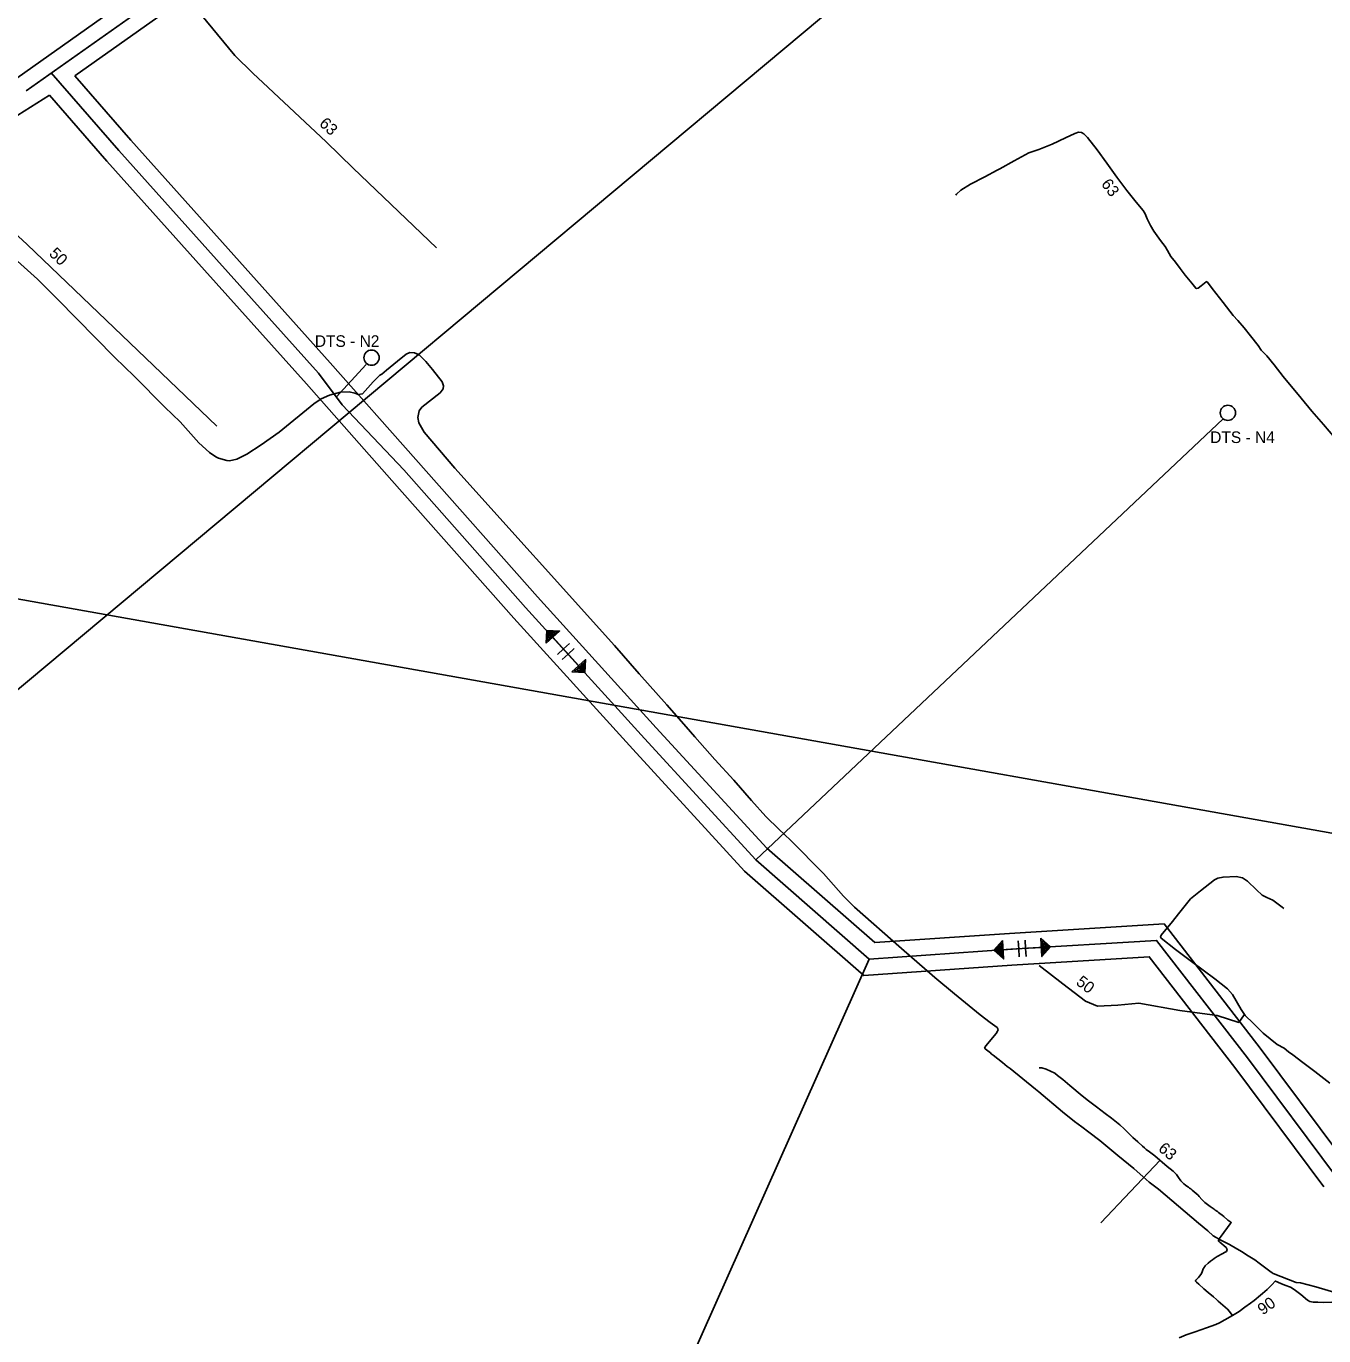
# Model space of a CAD drawing. Extents: x -444841 to -429545, y -1135312 to -1129851.
# Drawn here: x -442545 to -441650, y -1131866 to -1130962 of the extents above; entities that cross this region are included whole.
import ezdxf

# ---------------------------------------------------------------- set-up
doc = ezdxf.new("R2010")
doc.units = 0
for name, color, linetype in [('Vrstva 10', 7, 'Continuous'), ('Vrstva 15', 7, 'Continuous'), ('Vrstva 18', 7, 'Continuous'), ('Vrstva 19', 7, 'Continuous'), ('Vrstva 21', 7, 'Continuous'), ('Vrstva 27', 7, 'Continuous'), ('Vrstva 30', 7, 'Continuous'), ('Vrstva 35', 7, 'Continuous'), ('Vrstva 38', 7, 'Continuous'), ('Vrstva 58', 7, 'Continuous'), ('Vrstva 59', 7, 'Continuous')]:
    doc.layers.add(name, color=color, linetype=linetype)

msp = doc.modelspace()

# ---------------------------------------------------------------- linework, layer by layer
at = {"layer": 'Vrstva 10'}
for p, q in [((-442174.36, -1131391.7), (-442170.21, -1131387.95)), ((-442178.52, -1131395.45), (-442174.36, -1131391.7)), ((-442175.33, -1131398.99), (-442171.17, -1131395.23)), ((-442171.17, -1131395.23), (-442167.02, -1131391.48)), ((-441860.49, -1131593), (-441860.15, -1131598.59)), ((-441860.15, -1131598.59), (-441859.81, -1131604.18)), ((-441855.74, -1131592.71), (-441855.4, -1131598.3)), ((-441855.4, -1131598.3), (-441855.06, -1131603.89))]:
    msp.add_line(p, q, dxfattribs=at)
for points in [[(-442545.2, -1131006.71), (-442443.5, -1130934.6), (-442365.65, -1130877.08), (-442301.93, -1130826.75), (-442234.54, -1130772.43), (-442143.45, -1130703.1), (-442064.73, -1130644.42), (-442003.9, -1130597.89), (-441963.63, -1130563.69)], [(-441640.89, -1131756.15), (-441702.27, -1131673.76), (-441764.98, -1131592.78), (-441865.73, -1131598.93), (-441963.38, -1131605.66), (-442041.7, -1131537.14), (-442118.49, -1131453.57), (-442200.5, -1131363.12), (-442284.59, -1131268.2), (-442327.18, -1131223.28), (-442343.56, -1131201.55), (-442413.9, -1131123), (-442481.24, -1131047.9), (-442527.87, -1130994.29)], [(-442163.85, -1131403.34), (-442172.77, -1131393.47), (-442181.68, -1131383.6)], [(-441871.05, -1131599.25), (-441857.78, -1131598.44), (-441844.5, -1131597.63)]]:
    msp.add_lwpolyline(points, dxfattribs=at)
for points in [[(-442186.36, -1131387.82), (-442185.91, -1131378.92), (-442177.01, -1131379.37)], [(-442185.57, -1131386.17), (-442185.24, -1131379.65), (-442178.73, -1131379.99)], [(-442184.79, -1131384.51), (-442184.58, -1131380.39), (-442180.45, -1131380.6)], [(-442184, -1131382.86), (-442183.92, -1131381.12), (-442182.18, -1131381.21)], [(-442168.53, -1131407.56), (-442159.18, -1131399.11), (-442159.63, -1131408.01)], [(-442166.81, -1131406.95), (-442159.96, -1131400.77), (-442160.3, -1131407.28)], [(-442165.08, -1131406.33), (-442160.75, -1131402.42), (-442160.96, -1131406.54)], [(-442163.36, -1131405.72), (-442161.53, -1131404.07), (-442161.62, -1131405.81)], [(-441871.43, -1131592.97), (-441870.67, -1131605.54), (-441877.34, -1131599.64)], [(-441872.03, -1131594.7), (-441871.47, -1131603.9), (-441876.35, -1131599.58)], [(-441872.63, -1131596.43), (-441872.27, -1131602.26), (-441875.36, -1131599.52)], [(-441873.22, -1131598.16), (-441873.07, -1131600.61), (-441874.37, -1131599.46)], [(-441844.88, -1131591.35), (-441838.21, -1131597.25), (-441844.12, -1131603.92)], [(-441844.08, -1131592.99), (-441839.2, -1131597.31), (-441843.52, -1131602.19)], [(-441843.28, -1131594.63), (-441840.19, -1131597.37), (-441842.92, -1131600.46)], [(-441842.48, -1131596.28), (-441841.18, -1131597.43), (-441842.33, -1131598.73)]]:
    msp.add_lwpolyline(points, close=True, dxfattribs=at)
at = {"layer": 'Vrstva 15'}
for points in [[(-441968.62, -1130553.5), (-442010.81, -1130589.32), (-442071.36, -1130635.64), (-442150.07, -1130694.32), (-442241.33, -1130763.77), (-442308.79, -1130818.15), (-442372.32, -1130868.34), (-442449.95, -1130925.69), (-442551.7, -1130997.84)], [(-442511.53, -1130996.32), (-442437.05, -1130943.51), (-442358.97, -1130885.82), (-442295.07, -1130835.35), (-442227.76, -1130781.09), (-442136.83, -1130711.89), (-442058.1, -1130653.2), (-441997, -1130606.45), (-441954.08, -1130570.1)], [(-441638.65, -1131740.75), (-441693.51, -1131667.11), (-441759.84, -1131581.45), (-441866.44, -1131587.95), (-441959.57, -1131594.37), (-442034.01, -1131529.25), (-442110.37, -1131446.15), (-442192.31, -1131355.77), (-442276.35, -1131260.91), (-442335.34, -1131194.23), (-442405.71, -1131115.66), (-442473, -1131040.62), (-442511.53, -1130996.32)], [(-442958.88, -1131275.41), (-442890.15, -1131235.32), (-442810.27, -1131186.67), (-442739.92, -1131142.22), (-442669.31, -1131097.85), (-442529.12, -1131009.62)], [(-442529.12, -1131009.62), (-442489.49, -1131055.18), (-442422.09, -1131130.34), (-442351.77, -1131208.86), (-442292.83, -1131275.49), (-442208.69, -1131370.46), (-442126.61, -1131460.98), (-442049.4, -1131545.02), (-441967.18, -1131616.95), (-441865.01, -1131609.91), (-441770.12, -1131604.11), (-441711.03, -1131680.42), (-441649.71, -1131762.72)]]:
    msp.add_lwpolyline(points, dxfattribs=at)
at = {"layer": 'Vrstva 18'}
for p, q in [((-442331.31, -1131217.98), (-442310.54, -1131195.57)), ((-442041.7, -1131537.14), (-441719.12, -1131232.85))]:
    msp.add_line(p, q, dxfattribs=at)
msp.add_lwpolyline([(-441963.38, -1131605.66), (-442140.99, -1132004.1)], dxfattribs=at)
at = {"layer": 'Vrstva 19'}
for centre in [(-442306.82, -1131190.76), (-441715.81, -1131228.8)]:
    msp.add_circle(centre, 5.25, dxfattribs=at)
at = {"layer": 'Vrstva 27'}
for points in [[(-441875, -1131061.4), (-441873.22, -1131060.47), (-441863.4, -1131054.93), (-441853.15, -1131049.52), (-441846.2, -1131047.08), (-441837.16, -1131043.56), (-441827.99, -1131039.06), (-441821.56, -1131036.07), (-441819.04, -1131035.27), (-441816.85, -1131035.38), (-441815.18, -1131036.37), (-441812.78, -1131038.83), (-441806.15, -1131047.45), (-441799.35, -1131056.6), (-441792.46, -1131066.2), (-441785.62, -1131075.31), (-441779.19, -1131083.48), (-441774.38, -1131089.22), (-441772.99, -1131091.42), (-441771.52, -1131094.92), (-441769.3, -1131099.54), (-441766.95, -1131103.39), (-441762.41, -1131109.89), (-441759.14, -1131114.06), (-441757.49, -1131116.89), (-441755.12, -1131121.02), (-441752, -1131124.76), (-441748.72, -1131129.31), (-441745.34, -1131133.78), (-441740.68, -1131139.3), (-441737.95, -1131142.73), (-441737.21, -1131143.02), (-441736.44, -1131142.78), (-441734.34, -1131141.12), (-441730.88, -1131138.39), (-441730.56, -1131138.3), (-441729.97, -1131138.68), (-441726.59, -1131143.08), (-441719.01, -1131152.59), (-441714.38, -1131158.58), (-441712.29, -1131161.6), (-441708.97, -1131165.19), (-441704.68, -1131170.19), (-441700.18, -1131175.62), (-441695, -1131182.34), (-441692.77, -1131185.61), (-441689.06, -1131189.44), (-441683.85, -1131195.69), (-441677.61, -1131203.78), (-441665.21, -1131218.64), (-441657.99, -1131227.58), (-441649.8, -1131236.79), (-441641.93, -1131246.03)], [(-441903.67, -1131078.69), (-441903.19, -1131078.02), (-441900.11, -1131075.28), (-441893.57, -1131071.09), (-441883.59, -1131065.89), (-441875, -1131061.4)], [(-441677.05, -1131667.1), (-441681.74, -1131664.53), (-441691.56, -1131656.81), (-441698.48, -1131649.99), (-441703.98, -1131644.56), (-441706.67, -1131640.55), (-441712.54, -1131630.2), (-441716.1, -1131626.14), (-441724.86, -1131619.43), (-441740.92, -1131607.3), (-441751.9, -1131599.07), (-441761.84, -1131591.38), (-441762.23, -1131590.27), (-441761.86, -1131589.31), (-441754.11, -1131579.71), (-441749.83, -1131574.51), (-441741.54, -1131564.08), (-441734.68, -1131558.56), (-441724.97, -1131550.93), (-441722.83, -1131549.96), (-441719.18, -1131549.09), (-441710.07, -1131548.75), (-441705.83, -1131549.58), (-441702.35, -1131551.9), (-441696.03, -1131557.86), (-441692.11, -1131561.49), (-441688.84, -1131563.18), (-441684.74, -1131565.09), (-441678.31, -1131569.88), (-441677.22, -1131570.76)], [(-441645.5, -1131691.28), (-441655.91, -1131683.37), (-441664.13, -1131677.07), (-441671.03, -1131671.77), (-441673.89, -1131669.63), (-441677.05, -1131667.1)], [(-441778.09, -1131731.82), (-441781.51, -1131728.74), (-441784.55, -1131725.48), (-441787.48, -1131722.84), (-441790.45, -1131720.04), (-441796.07, -1131715.42), (-441800.54, -1131712.22), (-441806.49, -1131707.75), (-441811.96, -1131703.41), (-441816.33, -1131699.98), (-441824.88, -1131692.93), (-441829.74, -1131688.85), (-441833.36, -1131685.95), (-441835.37, -1131684.48), (-441838.32, -1131682.96), (-441841.3, -1131681.74), (-441844.18, -1131680.75), (-441846.02, -1131680.63)], [(-441714.64, -1131848.83), (-441716.18, -1131847.28), (-441722.46, -1131841.71), (-441723.65, -1131840.48), (-441725.7, -1131838.67), (-441729.35, -1131835.67), (-441732.35, -1131833.15), (-441735.86, -1131829.93), (-441737.44, -1131828.68), (-441738.07, -1131827.89), (-441738.15, -1131827.59), (-441737.93, -1131827.29), (-441737.16, -1131826.46), (-441736.19, -1131825.49), (-441735.34, -1131824.45), (-441734.51, -1131823.27), (-441733.87, -1131822.18), (-441733.31, -1131820.76), (-441732.8, -1131819.51), (-441732.31, -1131818.59), (-441732.08, -1131818), (-441731.4, -1131817.26), (-441729.46, -1131815.57), (-441727.76, -1131814.05), (-441726.54, -1131813.14), (-441725.31, -1131812.24), (-441723.32, -1131811.01), (-441719.69, -1131809.01), (-441717.62, -1131807.85), (-441716.88, -1131807.37), (-441716.51, -1131806.76), (-441716.33, -1131806.21), (-441716.49, -1131805.55), (-441717.02, -1131804.65), (-441721.46, -1131800.94), (-441721.81, -1131800.65), (-441722.36, -1131800.29), (-441722.32, -1131800.12), (-441721.73, -1131798.8), (-441721.12, -1131797.68), (-441720.42, -1131796.86), (-441714.14, -1131788.4), (-441713.53, -1131787.48), (-441713.87, -1131787.25), (-441715.93, -1131785.72), (-441718.62, -1131783.26), (-441719.69, -1131782.46), (-441721.29, -1131781.26), (-441721.47, -1131781.12), (-441722.27, -1131780.52), (-441723.08, -1131779.94), (-441724.54, -1131778.89), (-441725.38, -1131778.23), (-441728.11, -1131776.38), (-441730.86, -1131774.3), (-441731.66, -1131773.7), (-441732.4, -1131773.03), (-441733.91, -1131771.66), (-441735.61, -1131769.57), (-441736.43, -1131768.57), (-441740.45, -1131765.1), (-441741.48, -1131764.29), (-441742.27, -1131763.68), (-441743.07, -1131763.08), (-441744.2, -1131762.26), (-441745, -1131761.66), (-441746.12, -1131760.72), (-441747.38, -1131759.55), (-441748.31, -1131758.62), (-441749.84, -1131756.32), (-441751.2, -1131754.38), (-441753.62, -1131752.04), (-441757.73, -1131748.72), (-441766.25, -1131741.49), (-441769.82, -1131738.66), (-441772.21, -1131737.04), (-441773.41, -1131735.93), (-441774.75, -1131734.77), (-441778.09, -1131731.82)], [(-441644.14, -1131842.32), (-441650.08, -1131842.58), (-441653.81, -1131842.37), (-441657.06, -1131842.37), (-441659.27, -1131841.91), (-441660.97, -1131840.95), (-441665.56, -1131837.14), (-441670.12, -1131833.73), (-441672.62, -1131832.06), (-441676.47, -1131830.66), (-441679.32, -1131829.54), (-441682.91, -1131828.01), (-441683.13, -1131827.84), (-441685.21, -1131830.25), (-441688.69, -1131833.76), (-441692.01, -1131836.51), (-441693.38, -1131837.62), (-441697.71, -1131841.22), (-441700.24, -1131843.05), (-441704.09, -1131845.96), (-441708.05, -1131848.84), (-441712.67, -1131851.56)], [(-441749.53, -1131867.03), (-441744.56, -1131864.94), (-441738.43, -1131862.86), (-441730.56, -1131860.18), (-441724.24, -1131857.76), (-441721.62, -1131856.69), (-441717.82, -1131854.67), (-441712.67, -1131851.56)], [(-441712.67, -1131851.56), (-441712.87, -1131851.32), (-441714.64, -1131848.83)]]:
    msp.add_lwpolyline(points, dxfattribs=at)
at = {"layer": 'Vrstva 35'}
msp.add_line((-441762.67, -1131744.46), (-441803.48, -1131787.61), dxfattribs=at)
for points in [[(-442500.2, -1130884.37), (-442497.82, -1130887.18), (-442490.69, -1130893.39), (-442475.17, -1130905.39), (-442465.35, -1130912.21), (-442448.01, -1130925.49), (-442401.17, -1130982.2), (-442388.78, -1130994.41), (-442378.11, -1131004.41), (-442338.15, -1131041.79), (-442319.45, -1131059.9), (-442262, -1131115.01)], [(-442579.28, -1131080.66), (-442544.45, -1131112.65), (-442413.67, -1131238.08)], [(-441846.09, -1131610.06), (-441829.73, -1131622.78), (-441814.04, -1131634.63), (-441805.75, -1131638.18), (-441791.83, -1131637.59), (-441777.32, -1131636.11), (-441748.9, -1131641.14), (-441723.14, -1131644.69), (-441708.34, -1131649.43), (-441704.49, -1131644.1)]]:
    msp.add_lwpolyline(points, dxfattribs=at)
at = {"layer": 'Vrstva 58'}
for points in [[(-442370.7, -1131242.11), (-442383.11, -1131250.83), (-442393.02, -1131257.25), (-442399.76, -1131260.77), (-442404.88, -1131261.84), (-442406.71, -1131261.8), (-442412.56, -1131260.12), (-442414.38, -1131259.16), (-442418.63, -1131256.26), (-442426.13, -1131249.41), (-442439, -1131235.11), (-442449.42, -1131224.85), (-442470.74, -1131203.49), (-442483.95, -1131190.75), (-442523.5, -1131150.46), (-442537.44, -1131136.66), (-442565.49, -1131111.48)], [(-441878.57, -1131671.56), (-441879.15, -1131671.08), (-441879.67, -1131670.49), (-441883.29, -1131667.73), (-441883.76, -1131667.27), (-441882.79, -1131665.56), (-441875.82, -1131657.15), (-441874.74, -1131655.41), (-441874.6, -1131654.98), (-441874.47, -1131654.2), (-441875.13, -1131652.96), (-441879.88, -1131649.48), (-441886.68, -1131644.17), (-441896.93, -1131635.89), (-441904.52, -1131629.61), (-441918.17, -1131618.47), (-441941.18, -1131598.43), (-441973.52, -1131569.86), (-441981.08, -1131562.19), (-441994.91, -1131546.64), (-442017.52, -1131523.79), (-442021.76, -1131519.65), (-442025.5, -1131516.35), (-442034.65, -1131507.26), (-442044.54, -1131496.24), (-442056.79, -1131482.15), (-442069.96, -1131467.94), (-442083.78, -1131452.29), (-442089.65, -1131445.52), (-442103.04, -1131430.28), (-442122.21, -1131408.93), (-442139.14, -1131389.4), (-442249.3, -1131266.93), (-442270.62, -1131242.09), (-442274.13, -1131235.78), (-442274.83, -1131232.11), (-442273.93, -1131227.55), (-442272.18, -1131225.01), (-442259.54, -1131215.03), (-442257.47, -1131212.37), (-442257.15, -1131210.23), (-442258.02, -1131207.46), (-442264.72, -1131198.94), (-442269.34, -1131193.48), (-442274.03, -1131188.8), (-442277.23, -1131187.35), (-442280.51, -1131187.29), (-442282.85, -1131188.39), (-442288.89, -1131193.15), (-442296.43, -1131199.36), (-442299.72, -1131202.19), (-442300.16, -1131202.36), (-442300.36, -1131202.6), (-442300.75, -1131202.71), (-442301.09, -1131202.9), (-442305.78, -1131207.45), (-442313.2, -1131215.69), (-442316, -1131216.12), (-442318.29, -1131215.25), (-442322.38, -1131214.39), (-442328.3, -1131214.56), (-442335.84, -1131216.67), (-442341.56, -1131219.24), (-442346.59, -1131222.55), (-442370.7, -1131242.11)], [(-441638.02, -1131836.83), (-441655.24, -1131831.82), (-441665.71, -1131829.16), (-441668.69, -1131828.93), (-441684.67, -1131822.68), (-441685.22, -1131822.25), (-441686.81, -1131821.03), (-441694.23, -1131815.47), (-441697.16, -1131813.15), (-441702.91, -1131809.66), (-441705.91, -1131807.71), (-441709.65, -1131805.7), (-441714.68, -1131802.65), (-441719.2, -1131800.22), (-441720.67, -1131799.7), (-441723.83, -1131797.78), (-441726.03, -1131796.59), (-441729.61, -1131793.13), (-441736.02, -1131787.93), (-441745.38, -1131780.14), (-441763.65, -1131764.4), (-441770.18, -1131759.64), (-441774.35, -1131755.93), (-441780.7, -1131750.14), (-441791.7, -1131741.33), (-441804.3, -1131730.85), (-441811.89, -1131725.23), (-441816.66, -1131721.36), (-441821.8, -1131717.65), (-441829.96, -1131711.09), (-441846.23, -1131697.37), (-441848.57, -1131695.52), (-441866.12, -1131681.21), (-441868.12, -1131679.75), (-441871.49, -1131677.15), (-441877.91, -1131671.96), (-441878.57, -1131671.56)]]:
    msp.add_lwpolyline(points, dxfattribs=at)
at = {"layer": 'Vrstva 59'}
for points in [[(-441161.73, -1130257.99), (-444840.51, -1133333.5)], [(-440690.16, -1131688.83), (-443044.68, -1131269.31), (-443119.43, -1131255.99)]]:
    msp.add_lwpolyline(points, dxfattribs=at)

# ---------------------------------------------------------------- texts
at = {"layer": 'Vrstva 21'}
for s, p in [('DTS - N2', (-442346, -1131183.32)), ('DTS - N4', (-441728.03, -1131249.65))]:
    msp.add_text(s, height=8, dxfattribs=at).set_placement(p)
at = {"layer": 'Vrstva 30'}
for s, rotation, p in [('63', 306.90007, (-441803.66, -1131070.99)), ('63', 319.68235, (-441764.46, -1131737.39)), ('90', 35.87897, (-441691.74, -1131851.62))]:
    msp.add_text(s, height=8, rotation=rotation, dxfattribs=at).set_placement(p)
at = {"layer": 'Vrstva 38'}
for s, rotation, p in [('63', 316.91211, (-442343.48, -1131029.96)), ('50', 316.195, (-442529.93, -1131119.64)), ('50', 322.01317, (-441821.23, -1131622.69))]:
    msp.add_text(s, height=8, rotation=rotation, dxfattribs=at).set_placement(p)

doc.saveas('drawing.dxf')
